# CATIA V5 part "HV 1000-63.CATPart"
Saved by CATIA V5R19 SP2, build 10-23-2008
Part number: HV 1000-63
Bounding box of the stored display mesh (mm): x -24.865 to 24.865, y -24.997 to 24.997, z 0 to 183
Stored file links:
  C:\Users\Bora\Desktop\3D KATI MODEL- CATIA PART\HV serisi\HV 1000\HV 1000-63.CATPart
  C:\Program Files\Dassault Systemes\B19\intel_a\reffiles\standard\MetricThickPitch.txt
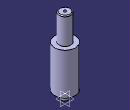
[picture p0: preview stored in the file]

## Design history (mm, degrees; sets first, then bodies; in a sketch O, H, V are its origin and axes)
Body1 (main body)
  Sketch1 on yz-plane, origin (0, 0, 0), H (0, 1, 0), V (0, 0, 1)
    point P1 (14, 181)
    point P3 (14, 181)
    point P8 (8, 17)
    point P10 (8, 1)
    point P11 (8, 17)
    point P12 (8, 1)
    arc A1 centre (12, 181) radius 2 from (14, 181) to (12, 183) ccw
    line L1 (14, 181) -> (14, 119)
    arc A2 centre (8, 18) radius 1 from (8, 19) to (8, 17) ccw
    line L2 (7, 0) -> (8, 1)
    line L3 (8, 17) -> (8, 1)
    line L4 (0, 0) -> (7, 0)
    line L5 (8, 19) -> (25, 19)
    line L6 (14, 119) -> (25, 119)
    line L7 (12, 183) -> (0, 183)
    point P13 (0, 183)
    line L8 (25, 119) -> (25, 19)
    horizontal: L4 H, L5 H, L6 H
    coincidence: P13 V, P1 P3, P8 P11, P10 P12
    tangency: L7 A1
    vertical: L8 V
  Shaft1: profile Sketch1, axis Sketch1.V, angle 360
  Sketch2 on face of Shaft1 from Sketch1.L4, origin (0, 0, 0), H (1, 0, 0), V (0, -1, 0)
    point P1 (0, 0)
  Hole1: placed by Sketch2, at (0, 0, 0) direction (0, 0, 1), diameter 13.835, depth 19, threaded "M16", thread diameter 16, thread depth 19, pitch 2
  Sketch3 on face of Shaft1 from Sketch1.L7, origin (0, 0, 183), H (1, 0, 0), V (0, 1, 0)
    point P1 (0, 0)
  Hole2: placed by Sketch3, at (0, 0, 183) direction (0, 0, -1), diameter 6.647, depth 15, threaded "M8", thread diameter 8, thread depth 15, pitch 1.25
